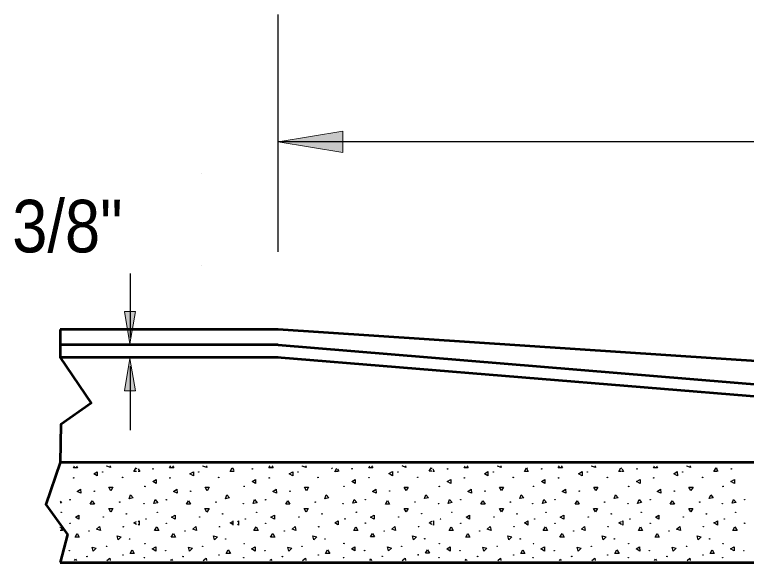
# Model space of a CAD drawing. Extents: x 75.6 to 110.9, y 28 to 50.
# Drawn here: x 93.721 to 95.81, y 39.251 to 40.813 of the extents above; entities that cross this region are included whole.
import ezdxf
from ezdxf.enums import TextEntityAlignment as Align

# ---------------------------------------------------------------- set-up
doc = ezdxf.new("R2010")
doc.units = 0
doc.header["$LTSCALE"] = 0.06
doc.layers.add('1', color=7, linetype='Continuous', lineweight=25)
doc.layers.add('3', color=7, linetype='Continuous', lineweight=13)

msp = doc.modelspace()

# ---------------------------------------------------------------- hatches: boundary and pattern name
at = {"layer": '3'}
for points in [[(94.65833, 40.48075), (94.65833, 40.41933), (94.47375, 40.45008), (94.47375, 40.45008)], [(94.06592, 39.96667), (94.03517, 39.96667), (94.05058, 39.87433), (94.05058, 39.87433)], [(94.06592, 39.74), (94.03517, 39.74), (94.05058, 39.83233), (94.05058, 39.83233)]]:
    msp.add_hatch(color=256, dxfattribs=at).paths.add_polyline_path(points)

# ---------------------------------------------------------------- linework, layer by layer
at = {"layer": '1'}
for p, q in [((94.47375, 40.136), (94.47375, 40.81275)), ((97.46283, 40.45008), (94.47375, 40.45008)), ((93.88908, 39.52017), (93.89242, 39.526)), ((93.89742, 39.526), (93.90075, 39.52017)), ((93.98425, 39.52533), (93.98492, 39.526)), ((93.99525, 39.52133), (93.98425, 39.52533)), ((93.99442, 39.526), (93.99525, 39.52133)), ((94.16367, 39.52017), (94.167, 39.526)), ((94.172, 39.526), (94.17533, 39.52017)), ((94.25883, 39.52533), (94.25958, 39.526)), ((94.26983, 39.52133), (94.25883, 39.52533)), ((94.269, 39.526), (94.26983, 39.52133)), ((94.44725, 39.52017), (94.45058, 39.526)), ((94.45558, 39.526), (94.45892, 39.52017)), ((94.54242, 39.52533), (94.54308, 39.526)), ((94.55333, 39.52133), (94.54242, 39.52533)), ((94.55258, 39.526), (94.55333, 39.52133)), ((94.732, 39.5205), (94.73533, 39.52625)), ((94.74025, 39.52625), (94.74358, 39.5205)), ((94.82717, 39.52567), (94.82783, 39.52625)), ((94.83808, 39.52167), (94.82717, 39.52567)), ((94.83725, 39.52625), (94.83808, 39.52167)), ((95.00442, 39.52025), (95.00775, 39.526)), ((95.01267, 39.526), (95.016, 39.52025)), ((95.09958, 39.52542), (95.10025, 39.526)), ((95.1105, 39.52142), (95.09958, 39.52542)), ((95.10967, 39.526), (95.1105, 39.52142)), ((95.27325, 39.52025), (95.27658, 39.526)), ((95.28158, 39.526), (95.28492, 39.52025)), ((95.36842, 39.52542), (95.36908, 39.526)), ((95.37933, 39.52142), (95.36842, 39.52542)), ((95.37858, 39.526), (95.37933, 39.52142)), ((95.545, 39.52025), (95.54833, 39.526)), ((95.55325, 39.526), (95.55658, 39.52025)), ((95.64017, 39.52542), (95.64083, 39.526)), ((95.65108, 39.52142), (95.64017, 39.52542)), ((95.65025, 39.526), (95.65108, 39.52142)), ((93.90075, 39.52017), (93.88908, 39.52017)), ((94.06192, 39.51033), (94.06775, 39.52033)), ((94.06958, 39.51033), (94.06192, 39.51033)), ((94.06775, 39.52033), (94.06958, 39.51717)), ((94.07425, 39.51717), (94.07825, 39.51033)), ((94.07825, 39.51033), (94.07425, 39.51033)), ((94.17533, 39.52017), (94.16367, 39.52017)), ((94.33658, 39.51033), (94.34233, 39.52033)), ((94.34425, 39.51033), (94.33658, 39.51033)), ((94.34233, 39.52033), (94.34425, 39.51717)), ((94.34292, 39.52033), (94.34692, 39.5135)), ((94.34792, 39.51033), (94.344, 39.51033)), ((94.45892, 39.52017), (94.44725, 39.52017)), ((94.62592, 39.52033), (94.62783, 39.51717)), ((94.63492, 39.50925), (94.64075, 39.51933)), ((94.64367, 39.51033), (94.636, 39.51033)), ((94.64258, 39.51742), (94.6465, 39.51067)), ((94.6465, 39.51067), (94.64258, 39.51067)), ((94.74358, 39.5205), (94.732, 39.5205)), ((94.90483, 39.51067), (94.91058, 39.52067)), ((94.91258, 39.51067), (94.90483, 39.51067)), ((94.91058, 39.52067), (94.91258, 39.51742)), ((94.91492, 39.51717), (94.91892, 39.51033)), ((94.91892, 39.51033), (94.91492, 39.51033)), ((95.016, 39.52025), (95.00442, 39.52025)), ((95.17725, 39.51033), (95.183, 39.52042)), ((95.18492, 39.51033), (95.17725, 39.51033)), ((95.183, 39.52042), (95.18492, 39.51717)), ((95.18383, 39.51717), (95.18775, 39.51033)), ((95.18775, 39.51033), (95.18383, 39.51033)), ((95.28492, 39.52025), (95.27325, 39.52025)), ((95.44608, 39.51033), (95.45192, 39.52042)), ((95.45383, 39.51033), (95.44608, 39.51033)), ((95.45192, 39.52042), (95.45383, 39.51717)), ((95.45558, 39.51717), (95.4595, 39.51033)), ((95.4595, 39.51033), (95.45558, 39.51033)), ((95.55658, 39.52025), (95.545, 39.52025)), ((95.71783, 39.51033), (95.72358, 39.52042)), ((95.72558, 39.51033), (95.71783, 39.51033)), ((95.72358, 39.52042), (95.72558, 39.51717)), ((95.72517, 39.51725), (95.72908, 39.51042)), ((95.72908, 39.51042), (95.72517, 39.51042)), ((93.85133, 39.42575), (93.85533, 39.421)), ((93.85533, 39.421), (93.85133, 39.42033)), ((94.07425, 39.36758), (94.07658, 39.369)), ((94.07425, 39.36758), (94.07658, 39.369)), ((94.07658, 39.35733), (94.07425, 39.35867)), ((94.07658, 39.35733), (94.07425, 39.35867)), ((94.07658, 39.369), (94.07658, 39.35733)), ((94.07658, 39.369), (94.07658, 39.35733)), ((94.34417, 39.369), (94.34425, 39.35733)), ((94.35783, 39.36758), (94.36008, 39.369)), ((94.35783, 39.36758), (94.36008, 39.369)), ((94.36017, 39.35733), (94.35783, 39.35867)), ((94.36017, 39.35733), (94.35783, 39.35867)), ((94.36008, 39.369), (94.36017, 39.35733)), ((94.64258, 39.35867), (94.63492, 39.36317)), ((94.63592, 39.36425), (94.64367, 39.36867)), ((94.64258, 39.36792), (94.64483, 39.36925)), ((94.64258, 39.36792), (94.64483, 39.36925)), ((94.64492, 39.35758), (94.64258, 39.359)), ((94.64492, 39.35758), (94.64258, 39.359)), ((94.64483, 39.36925), (94.64492, 39.35758)), ((94.64483, 39.36925), (94.64492, 39.35758)), ((94.91492, 39.36767), (94.91725, 39.369)), ((94.91492, 39.36767), (94.91725, 39.369)), ((94.91725, 39.35733), (94.91492, 39.35867)), ((94.91725, 39.35733), (94.91492, 39.35867)), ((94.91725, 39.369), (94.91725, 39.35733)), ((94.91725, 39.369), (94.91725, 39.35733)), ((95.18383, 39.36767), (95.18608, 39.369)), ((95.18383, 39.36767), (95.18608, 39.369)), ((95.18617, 39.35733), (95.18383, 39.35867)), ((95.18617, 39.35733), (95.18383, 39.35867)), ((95.18608, 39.369), (95.18617, 39.35733)), ((95.18608, 39.369), (95.18617, 39.35733)), ((95.45558, 39.36767), (95.45783, 39.369)), ((95.45558, 39.36767), (95.45783, 39.369)), ((95.45792, 39.35733), (95.45558, 39.35867)), ((95.45792, 39.35733), (95.45558, 39.35867)), ((95.45783, 39.369), (95.45792, 39.35733)), ((95.45783, 39.369), (95.45792, 39.35733)), ((95.72517, 39.36767), (95.72742, 39.369)), ((95.72517, 39.36767), (95.72742, 39.369)), ((95.7275, 39.35733), (95.72517, 39.35875)), ((95.7275, 39.35733), (95.72517, 39.35875)), ((95.72742, 39.369), (95.7275, 39.35733)), ((95.72742, 39.369), (95.7275, 39.35733)), ((93.85133, 39.35033), (93.85225, 39.35183)), ((93.85808, 39.34175), (93.85133, 39.34175)), ((93.85225, 39.35183), (93.85808, 39.34175))]:
    msp.add_line(p, q, dxfattribs=at)
at = {"layer": '1', "lineweight": 53}
for p, q in [((94.47375, 39.91475), (93.85133, 39.91475)), ((97.47392, 39.71692), (94.47375, 39.91475)), ((94.47375, 39.87142), (93.85133, 39.87142)), ((94.47375, 39.87142), (97.48125, 39.62317)), ((94.47375, 39.83533), (93.85133, 39.83533)), ((94.47108, 39.8355), (97.48017, 39.59133)), ((97.938, 39.53517), (93.85133, 39.53517)), ((93.85133, 39.25083), (97.94517, 39.25083))]:
    msp.add_line(p, q, dxfattribs=at)
msp.add_lwpolyline([(93.85133, 39.91475), (93.85133, 39.83533), (93.93942, 39.70525), (93.85333, 39.64367), (93.85133, 39.53517), (93.81025, 39.416), (93.87183, 39.32992), (93.85133, 39.25083)], dxfattribs=at)
at = {"layer": '1'}
for points in [[(93.95725, 39.49775), (93.94717, 39.50358), (93.95725, 39.50942)], [(94.23183, 39.49775), (94.22175, 39.50358), (94.23183, 39.50942)], [(94.51542, 39.49775), (94.50525, 39.50358), (94.51533, 39.50942)], [(94.80017, 39.498), (94.79, 39.50392), (94.80008, 39.50975)], [(95.07258, 39.49775), (95.06242, 39.50367), (95.0725, 39.5095)], [(95.34142, 39.49775), (95.33125, 39.50367), (95.34133, 39.5095)], [(95.61317, 39.49775), (95.603, 39.50367), (95.61308, 39.5095)], [(94.1255, 39.47542), (94.11542, 39.48133), (94.12542, 39.48717)], [(94.409, 39.47542), (94.39892, 39.48133), (94.40892, 39.48717)], [(94.69383, 39.47575), (94.68367, 39.48158), (94.69367, 39.48742)], [(94.96625, 39.4755), (94.95608, 39.48133), (94.96608, 39.48717)], [(95.235, 39.4755), (95.22492, 39.48133), (95.23492, 39.48717)], [(95.50683, 39.4755), (95.49667, 39.48133), (95.50667, 39.48717)], [(95.77642, 39.47558), (95.76625, 39.48133), (95.77625, 39.48725)], [(93.99625, 39.45525), (93.99033, 39.46533), (94.002, 39.46533)], [(94.27083, 39.45525), (94.26492, 39.46533), (94.27658, 39.46533)], [(94.55433, 39.45525), (94.5485, 39.46533), (94.56017, 39.46533)], [(94.83908, 39.45558), (94.83325, 39.46567), (94.84492, 39.46567)], [(95.1115, 39.45533), (95.10558, 39.46533), (95.11725, 39.46533)], [(95.38033, 39.45533), (95.3745, 39.46533), (95.38617, 39.46533)], [(95.65208, 39.45533), (95.64625, 39.46533), (95.65792, 39.46533)], [(93.9105, 39.44767), (93.89992, 39.45258), (93.90942, 39.45925)], [(94.05992, 39.43442), (94.0485, 39.43242), (94.05242, 39.44333)], [(94.18508, 39.44767), (94.17458, 39.45258), (94.184, 39.45925)], [(94.33458, 39.43442), (94.32308, 39.43242), (94.327, 39.44333)], [(94.46858, 39.44767), (94.45808, 39.45258), (94.46758, 39.45925)], [(94.61808, 39.43442), (94.60658, 39.43242), (94.61058, 39.44333)], [(94.75342, 39.448), (94.74283, 39.45292), (94.75233, 39.45958)], [(94.90283, 39.43475), (94.89142, 39.43275), (94.89533, 39.44367)], [(95.02583, 39.44775), (95.01525, 39.45267), (95.02475, 39.45933)], [(95.17525, 39.4345), (95.16383, 39.4325), (95.16775, 39.44333)], [(95.29458, 39.44775), (95.28408, 39.45267), (95.29358, 39.45933)], [(95.44408, 39.4345), (95.43258, 39.4325), (95.43658, 39.44333)], [(95.56642, 39.44775), (95.55583, 39.45267), (95.56533, 39.45933)], [(95.71583, 39.4345), (95.70442, 39.4325), (95.70833, 39.44333)], [(93.94883, 39.41633), (93.93717, 39.41633), (93.94292, 39.42642)], [(94.12992, 39.421), (94.1185, 39.419), (94.12242, 39.43)], [(94.22342, 39.41633), (94.21175, 39.41633), (94.21758, 39.42642)], [(94.4135, 39.421), (94.402, 39.419), (94.406, 39.43)], [(94.50692, 39.41633), (94.49525, 39.41633), (94.50108, 39.42642)], [(94.69825, 39.42133), (94.68683, 39.41933), (94.69075, 39.43033)], [(94.79167, 39.41667), (94.78, 39.41667), (94.78583, 39.42675)], [(94.97058, 39.42108), (94.95925, 39.41908), (94.96317, 39.43)], [(95.06408, 39.41642), (95.05242, 39.41642), (95.05825, 39.4265)], [(95.2395, 39.42108), (95.228, 39.41908), (95.232, 39.43)], [(95.33292, 39.41642), (95.32125, 39.41642), (95.32708, 39.4265)], [(95.51125, 39.42108), (95.49983, 39.41908), (95.50375, 39.43)], [(95.60467, 39.41642), (95.593, 39.41642), (95.59883, 39.4265)], [(95.78083, 39.42117), (95.76942, 39.41917), (95.77333, 39.43008)], [(93.99575, 39.39433), (93.98992, 39.4045), (94.00158, 39.4045)], [(94.27033, 39.39433), (94.2645, 39.4045), (94.27617, 39.4045)], [(94.55392, 39.39433), (94.548, 39.4045), (94.55967, 39.4045)], [(94.83858, 39.39467), (94.83283, 39.40475), (94.84442, 39.40475)], [(95.111, 39.39442), (95.10525, 39.40458), (95.11683, 39.40458)], [(95.37992, 39.39442), (95.374, 39.40458), (95.38567, 39.40458)], [(95.65158, 39.39442), (95.64583, 39.40458), (95.65742, 39.40458)], [(93.90483, 39.37383), (93.89475, 39.37967), (93.90483, 39.3855)], [(94.17942, 39.37383), (94.16933, 39.37967), (94.17942, 39.3855)], [(94.463, 39.37383), (94.45292, 39.37967), (94.46292, 39.3855)], [(94.74775, 39.37417), (94.73758, 39.38), (94.74767, 39.38575)], [(95.02017, 39.37392), (95.01, 39.37975), (95.02008, 39.38558)], [(95.289, 39.37392), (95.27892, 39.37975), (95.28892, 39.38558)], [(95.56075, 39.37392), (95.55058, 39.37975), (95.56067, 39.38558)], [(93.966, 39.3415), (93.955, 39.3455), (93.96392, 39.353)], [(94.13267, 39.34175), (94.121, 39.34175), (94.12683, 39.35183)], [(94.24058, 39.3415), (94.22958, 39.3455), (94.23858, 39.353)], [(94.41625, 39.34175), (94.40458, 39.34175), (94.41042, 39.35183)], [(94.52417, 39.3415), (94.51325, 39.3455), (94.52208, 39.353)], [(94.701, 39.34208), (94.68933, 39.34208), (94.69517, 39.35217)], [(94.80892, 39.34175), (94.79792, 39.34575), (94.80683, 39.35325)], [(94.97342, 39.34183), (94.96175, 39.34183), (94.96758, 39.35192)], [(95.08125, 39.34158), (95.07033, 39.34558), (95.07925, 39.353)], [(95.24225, 39.34183), (95.23058, 39.34183), (95.23642, 39.35192)], [(95.35017, 39.34158), (95.33925, 39.34558), (95.34808, 39.353)], [(95.514, 39.34183), (95.50233, 39.34183), (95.50817, 39.35192)], [(95.62192, 39.34158), (95.61092, 39.34558), (95.61983, 39.353)], [(95.78358, 39.34192), (95.77192, 39.34192), (95.77775, 39.352)], [(93.90558, 39.32292), (93.89392, 39.32292), (93.89975, 39.333)], [(94.01717, 39.31517), (94.01417, 39.32633), (94.02542, 39.32333)], [(94.18025, 39.32292), (94.16858, 39.32292), (94.17433, 39.333)], [(94.29175, 39.31517), (94.28875, 39.32633), (94.3, 39.32333)], [(94.46375, 39.32292), (94.45208, 39.32292), (94.45792, 39.333)], [(94.57525, 39.31517), (94.57225, 39.32633), (94.58358, 39.32333)], [(94.7485, 39.32317), (94.73683, 39.32317), (94.74258, 39.33325)], [(94.86, 39.31542), (94.857, 39.32667), (94.86825, 39.32367)], [(95.02092, 39.323), (95.00925, 39.323), (95.015, 39.333)], [(95.13242, 39.31517), (95.12942, 39.32642), (95.14067, 39.32342)], [(95.28975, 39.323), (95.27808, 39.323), (95.28392, 39.333)], [(95.40125, 39.31517), (95.39825, 39.32642), (95.40958, 39.32342)], [(95.5615, 39.323), (95.54983, 39.323), (95.55558, 39.333)], [(95.673, 39.31517), (95.67, 39.32642), (95.68125, 39.32342)], [(93.94583, 39.28308), (93.94283, 39.29433), (93.954, 39.29133)], [(94.12442, 39.28317), (94.11425, 39.289), (94.12433, 39.29475)], [(94.22042, 39.28308), (94.21742, 39.29433), (94.22858, 39.29133)], [(94.40792, 39.28317), (94.39783, 39.289), (94.40792, 39.29475)], [(94.50392, 39.28308), (94.50092, 39.29433), (94.51225, 39.29133)], [(94.69267, 39.28342), (94.68258, 39.28925), (94.69258, 39.29508)], [(94.78867, 39.28333), (94.78567, 39.29467), (94.79692, 39.29167)], [(94.96508, 39.28317), (94.955, 39.289), (94.965, 39.29483)], [(95.06108, 39.28317), (95.05808, 39.29442), (95.06933, 39.29142)], [(95.23392, 39.28317), (95.22383, 39.289), (95.23392, 39.29483)], [(95.32992, 39.28317), (95.32692, 39.29442), (95.33825, 39.29142)], [(95.50567, 39.28317), (95.49558, 39.289), (95.50558, 39.29483)], [(95.60167, 39.28317), (95.59867, 39.29442), (95.60992, 39.29142)], [(95.77525, 39.28325), (95.76525, 39.289), (95.77525, 39.29492)], [(94.06258, 39.27633), (94.05092, 39.27633), (94.05667, 39.28633)], [(94.33717, 39.27633), (94.3255, 39.27633), (94.33125, 39.28633)], [(94.62067, 39.27633), (94.609, 39.27633), (94.61483, 39.28633)], [(94.90542, 39.27667), (94.89383, 39.27667), (94.89958, 39.28667)], [(95.17783, 39.27633), (95.16625, 39.27633), (95.172, 39.28642)], [(95.44667, 39.27633), (95.435, 39.27633), (95.44083, 39.28642)], [(95.71842, 39.27633), (95.70683, 39.27633), (95.71258, 39.28642)]]:
    msp.add_lwpolyline(points, close=True, dxfattribs=at)
for points in [[(94.06958, 39.35867), (94.06192, 39.36317), (94.06958, 39.36758)], [(94.34425, 39.35867), (94.3365, 39.36317), (94.34425, 39.36758)], [(94.91258, 39.359), (94.90483, 39.36342), (94.91258, 39.36792)], [(95.18492, 39.35867), (95.17725, 39.36317), (95.18492, 39.36767)], [(95.45383, 39.35867), (95.446, 39.36317), (95.45383, 39.36767)], [(95.72558, 39.35867), (95.71783, 39.36317), (95.72558, 39.36767)], [(93.89242, 39.256), (93.89492, 39.26025), (93.89742, 39.256)], [(93.98492, 39.256), (93.99317, 39.26283), (93.99442, 39.256)], [(93.98492, 39.256), (93.99317, 39.26283), (93.99442, 39.256)], [(94.167, 39.256), (94.1695, 39.26025), (94.172, 39.256)], [(94.25958, 39.256), (94.26775, 39.26283), (94.269, 39.256)], [(94.25958, 39.256), (94.26775, 39.26283), (94.269, 39.256)], [(94.45058, 39.256), (94.453, 39.26025), (94.45558, 39.256)], [(94.54308, 39.256), (94.55125, 39.26283), (94.55258, 39.256)], [(94.54308, 39.256), (94.55125, 39.26283), (94.55258, 39.256)], [(94.73533, 39.25625), (94.73783, 39.26058), (94.74025, 39.25625)], [(94.82783, 39.25625), (94.836, 39.26317), (94.83725, 39.25625)], [(94.82783, 39.25625), (94.836, 39.26317), (94.83725, 39.25625)], [(95.00775, 39.256), (95.01025, 39.26033), (95.01267, 39.256)], [(95.10025, 39.256), (95.10842, 39.26292), (95.10967, 39.256)], [(95.10025, 39.256), (95.10842, 39.26292), (95.10967, 39.256)], [(95.27658, 39.256), (95.279, 39.26033), (95.28158, 39.256)], [(95.36908, 39.256), (95.37725, 39.26292), (95.37858, 39.256)], [(95.36908, 39.256), (95.37725, 39.26292), (95.37858, 39.256)], [(95.54833, 39.256), (95.55083, 39.26033), (95.55325, 39.256)], [(95.64083, 39.256), (95.649, 39.26292), (95.65025, 39.256)], [(95.64083, 39.256), (95.649, 39.26292), (95.65025, 39.256)]]:
    msp.add_lwpolyline(points, dxfattribs=at)
for centre in [(93.97236, 39.50845), (94.11644, 39.51738), (94.24696, 39.50845), (94.39999, 39.51738), (94.53051, 39.50845), (94.68474, 39.51768), (94.81526, 39.50875), (94.95714, 39.51743), (95.08766, 39.5085), (95.22599, 39.51743), (95.35651, 39.5085), (95.49774, 39.51743), (95.62826, 39.5085), (95.76734, 39.51748), (93.88981, 39.49173), (94.02926, 39.49284), (94.16441, 39.49173), (94.30386, 39.49284), (94.44796, 39.49173), (94.58741, 39.49284), (94.73271, 39.49203), (94.87216, 39.49314), (95.00511, 39.49178), (95.14456, 39.49289), (95.27396, 39.49178), (95.41341, 39.49289), (95.54571, 39.49178), (95.68516, 39.49289), (94.09299, 39.46719), (94.37654, 39.46719), (94.66129, 39.46749), (94.93369, 39.46724), (95.20254, 39.46724), (95.47429, 39.46724), (95.74389, 39.46729), (93.94894, 39.4538), (94.22354, 39.4538), (94.50709, 39.4538), (94.79184, 39.4541), (95.06424, 39.45385), (95.33309, 39.45385), (95.60484, 39.45385), (93.87975, 39.42925), (94.02143, 39.42255), (94.15435, 39.42925), (94.29603, 39.42255), (94.4379, 39.42925), (94.57958, 39.42255), (94.72265, 39.42955), (94.86433, 39.42285), (94.99505, 39.4293), (95.13673, 39.4226), (95.2639, 39.4293), (95.40558, 39.4226), (95.53565, 39.4293), (95.67733, 39.4226), (95.80525, 39.42935), (94.09077, 39.41809), (94.37431, 39.41809), (94.65906, 39.41839), (94.93147, 39.41814), (95.20032, 39.41814), (95.47207, 39.41814), (95.74166, 39.41819), (93.8541, 39.39354), (93.97459, 39.38016), (94.0404, 39.38909), (94.1287, 39.39354), (94.24919, 39.38016), (94.315, 39.38909), (94.41225, 39.39354), (94.53274, 39.38016), (94.59855, 39.38909), (94.697, 39.39384), (94.81749, 39.38046), (94.8833, 39.38939), (94.9694, 39.39359), (95.08989, 39.38021), (95.1557, 39.38914), (95.23825, 39.39359), (95.35874, 39.38021), (95.42455, 39.38914), (95.51, 39.39359), (95.63049, 39.38021), (95.6963, 39.38914), (95.7796, 39.39364), (93.87975, 39.36231), (94.09635, 39.37458), (94.15435, 39.36231), (94.37989, 39.37458), (94.4379, 39.36231), (94.66464, 39.37488), (94.72265, 39.36261), (94.93704, 39.37463), (94.99505, 39.36236), (95.20589, 39.37463), (95.2639, 39.36236), (95.47764, 39.37463), (95.53565, 39.36236), (95.74724, 39.37468), (95.80525, 39.36241), (93.9333, 39.33999), (94.03149, 39.35228), (94.2079, 39.33999), (94.30609, 39.35228), (94.49145, 39.33999), (94.58964, 39.35228), (94.7762, 39.34029), (94.87439, 39.35258), (95.0486, 39.34004), (95.14679, 39.35233), (95.31745, 39.34004), (95.41564, 39.35233), (95.5892, 39.34004), (95.68739, 39.35233), (94.04933, 39.3177), (94.32393, 39.3177), (94.60748, 39.3177), (94.89223, 39.318), (95.16463, 39.31775), (95.43348, 39.31775), (95.70523, 39.31775), (93.98352, 39.29648), (94.09299, 39.30431), (94.25812, 39.29648), (94.37654, 39.30431), (94.54167, 39.29648), (94.66129, 39.30461), (94.82642, 39.29678), (94.93369, 39.30436), (95.09882, 39.29653), (95.20254, 39.30436), (95.36767, 39.29653), (95.47429, 39.30436), (95.63942, 39.29653), (95.74389, 39.30441), (93.87752, 39.28422), (94.15212, 39.28422), (94.43567, 39.28422), (94.72042, 39.28452), (94.99282, 39.28427), (95.26167, 39.28427), (95.53342, 39.28427), (95.80302, 39.28432), (93.92772, 39.26748), (94.03036, 39.27195), (94.09189, 39.26415), (94.20232, 39.26748), (94.30497, 39.27195), (94.37544, 39.26415), (94.48587, 39.26748), (94.58852, 39.27195), (94.66019, 39.26445), (94.77062, 39.26778), (94.87327, 39.27225), (94.93259, 39.2642), (95.04302, 39.26753), (95.14566, 39.272), (95.20144, 39.2642), (95.31187, 39.26753), (95.41452, 39.272), (95.47319, 39.2642), (95.58362, 39.26753), (95.68627, 39.272), (95.74279, 39.26425)]:
    msp.add_circle(centre, 0.000647, dxfattribs=at)
at = {"layer": '3'}
for p, q in [((94.25433, 40.3595), (94.25425, 40.3595)), ((94.25433, 40.0985), (94.25425, 40.0985))]:
    msp.add_line(p, q, dxfattribs=at)
at = {"layer": '3', "lineweight": 25}
for p, q in [((94.05225, 39.89225), (94.05225, 40.075)), ((94.05225, 39.62767), (94.05225, 39.81042))]:
    msp.add_line(p, q, dxfattribs=at)
at = {"layer": '3'}
for points in [[(94.65833, 40.48075), (94.65833, 40.41933), (94.47375, 40.45008), (94.47375, 40.45008)], [(94.06592, 39.96667), (94.03517, 39.96667), (94.05058, 39.87433), (94.05058, 39.87433)], [(94.06592, 39.74), (94.03517, 39.74), (94.05058, 39.83233), (94.05058, 39.83233)]]:
    msp.add_lwpolyline(points, close=True, dxfattribs=at)

# ---------------------------------------------------------------- texts
at = {"layer": '1', "width": 0.9}
msp.add_text('3/8"', height=0.15, dxfattribs=at).set_placement((93.87188, 40.13475), align=Align.CENTER)

doc.saveas('drawing.dxf')
